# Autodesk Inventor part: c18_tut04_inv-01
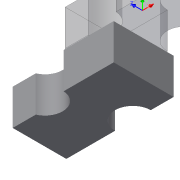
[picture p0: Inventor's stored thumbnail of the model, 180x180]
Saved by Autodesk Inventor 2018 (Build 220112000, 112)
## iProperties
Created: 2017-06
Part Number: c18_tut04_inv-01
Material: Generic
Document SubType Name: Modeling
Designer: CADCIM 00
Density: 1 g/cm^3
Appearance: Default
Author: CADCIM 00
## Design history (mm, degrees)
derived "c18_tut04_inv.ipt"
feature "Solid1::c18_tut04_inv.ipt"
tag "TaggingFeature1"
body "Solid1"
other parameters: "d2" = 16.66667, "d3" = 33.33333, "d4" = 0, "RAD" = 16.66667, "EXT" = 33.33333
